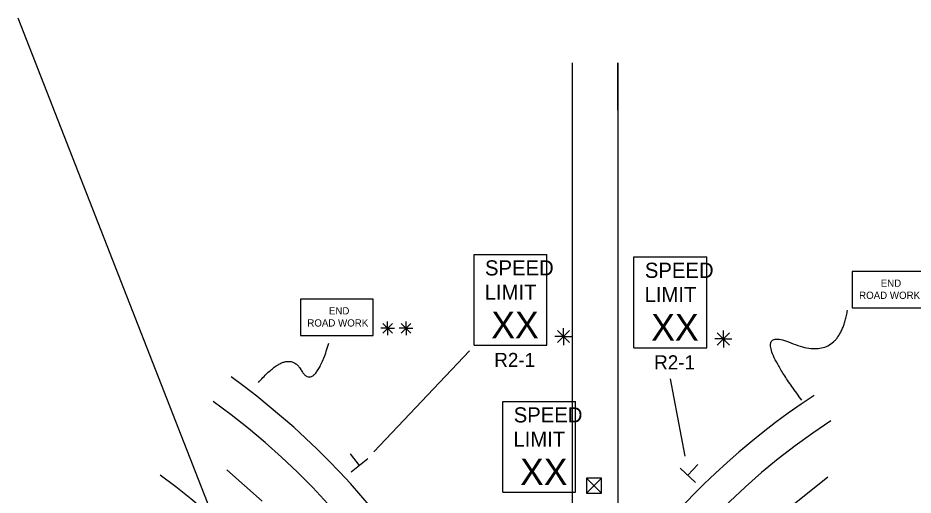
# Model space of a CAD drawing. Extents: x 16486 to 19505, y 5576 to 6998.
# Drawn here: x 16688.1 to 17160.6, y 6745.9 to 6997.8 of the extents above; entities that cross this region are included whole.
import ezdxf

# ---------------------------------------------------------------- set-up
doc = ezdxf.new("R2010")
doc.units = 0
for name, color, linetype in [('ALI_LEGAL_EX', 7, 'Continuous'), ('PAVT_EDGE_EX', 7, 'Continuous'), ('TRAFFIC_SIGNS_PR', 7, 'Continuous'), ('TYPICAL_TEXT_DIMEN_PR', 7, 'Continuous')]:
    doc.layers.add(name, color=color, linetype=linetype)

msp = doc.modelspace()

# ---------------------------------------------------------------- linework, layer by layer
at = {"layer": 'ALI_LEGAL_EX'}
for p, q in [((16688.08, 6997.81), (16910.11, 6429.44)), ((16980.68, 6974.12), (16980.68, 6155.98)), ((17004.68, 6974.12), (17004.68, 6155.98)), ((16980.68, 6922.21), (16980.68, 6058.3)), ((17004.68, 6922.21), (17004.68, 6058.3))]:
    msp.add_line(p, q, dxfattribs=at)
for points in [[(17004.68, 6949.12), (17004.68, 6974.12)], [(16817.07, 6742.72), (16798.4, 6759.35)], [(17096.1, 6739.95), (17115.56, 6755.65)]]:
    msp.add_lwpolyline(points, dxfattribs=at)
at = {"layer": 'PAVT_EDGE_EX'}
for centre, radius, start, end in [((16564.4, 6480.53), 404, 15.917, 54.2283), ((16564.4, 6480.53), 388, 0, 54.2283), ((17316.4, 6480.53), 380, 123.1879, 163.0483), ((17316.4, 6480.53), 364, 123.1879, 180), ((16564.4, 6480.53), 340, 0, 54.2283)]:
    msp.add_arc(centre, radius, start, end, dxfattribs=at)
at = {"layer": 'TRAFFIC_SIGNS_PR'}
for p, q in [((16928.82, 6873), (16967.22, 6873)), ((16928.82, 6825), (16928.82, 6873)), ((16967.22, 6825), (16967.22, 6873)), ((17013.23, 6871.74), (17051.63, 6871.74)), ((17013.23, 6823.74), (17013.23, 6871.74)), ((17051.63, 6823.74), (17051.63, 6871.74)), ((16928.82, 6825), (16967.22, 6825)), ((17013.23, 6823.74), (17051.63, 6823.74)), ((16944, 6795.43), (16982.4, 6795.43)), ((16944, 6747.43), (16944, 6795.43)), ((16982.4, 6747.43), (16982.4, 6795.43)), ((16944, 6747.43), (16982.4, 6747.43))]:
    msp.add_line(p, q, dxfattribs=at)
for points in [[(17128.46, 6844.75), (17166.86, 6844.75), (17166.86, 6863.95), (17128.46, 6863.95)], [(16837.22, 6830.16), (16875.62, 6830.16), (16875.62, 6849.36), (16837.22, 6849.36)]]:
    msp.add_lwpolyline(points, close=True, dxfattribs=at)
at = {"layer": 'TYPICAL_TEXT_DIMEN_PR'}
for p, q in [((16883.17, 6833.98), (16883.17, 6837.54)), ((16892.92, 6833.98), (16892.92, 6837.54)), ((16883.17, 6833.98), (16879.55, 6833.98)), ((16880.62, 6836.53), (16885.72, 6831.43)), ((16885.72, 6836.53), (16880.62, 6831.43)), ((16883.17, 6833.98), (16885.72, 6833.98)), ((16883.17, 6833.98), (16886.76, 6833.98)), ((16883.17, 6833.98), (16883.17, 6830.38)), ((16892.92, 6833.98), (16889.29, 6833.98)), ((16890.37, 6836.53), (16895.47, 6831.43)), ((16895.47, 6836.53), (16890.37, 6831.43)), ((16892.92, 6833.98), (16895.47, 6833.98)), ((16892.92, 6833.98), (16896.5, 6833.98)), ((16892.92, 6833.98), (16892.92, 6830.38)), ((16972.82, 6832.8), (16979.2, 6826.43)), ((16979.2, 6832.8), (16972.82, 6826.43)), ((16976.01, 6829.62), (16976.01, 6834.07)), ((17060.42, 6828.35), (17060.42, 6832.81)), ((16976.01, 6829.62), (16971.48, 6829.62)), ((16976.01, 6829.62), (16979.2, 6829.62)), ((16976.01, 6829.62), (16980.49, 6829.62)), ((16976.01, 6829.62), (16976.01, 6825.12)), ((17060.42, 6828.35), (17055.88, 6828.35)), ((17057.23, 6831.54), (17063.6, 6825.16)), ((17063.6, 6831.54), (17057.23, 6825.16)), ((17060.42, 6828.35), (17063.6, 6828.35)), ((17060.42, 6828.35), (17064.89, 6828.35)), ((17060.42, 6828.35), (17060.42, 6823.85)), ((16926.42, 6822.03), (16875.94, 6768.85)), ((17040.24, 6766.41), (17032.44, 6807.29)), ((16868.44, 6761.57), (16863.56, 6767.65)), ((16872.82, 6765.09), (16864.05, 6758.06)), ((17041.66, 6756.39), (17046.96, 6762.1)), ((17045.78, 6752.57), (17037.54, 6760.22)), ((16988.15, 6754.9), (16996.15, 6746.9)), ((16988.15, 6746.9), (16996.15, 6754.9))]:
    msp.add_line(p, q, dxfattribs=at)
msp.add_lwpolyline([(16988.15, 6754.9), (16988.15, 6746.9), (16996.15, 6746.9), (16996.15, 6754.9)], close=True, dxfattribs=at)
for points in [[(17101.86, 6795.98), (17071.58, 6836.6), (17121.54, 6815.63), (17125.94, 6843.59)], [(16815.05, 6805.35), (16830.8, 6823.7), (16844.29, 6800.22), (16852.21, 6826.08)]]:
    msp.add_open_spline(points, degree=2, dxfattribs=at)

# ---------------------------------------------------------------- texts
at = {"layer": 'TRAFFIC_SIGNS_PR'}
for s, height, p in [('SPEED', 8, (16934.59, 6861.86)), ('SPEED', 8, (17018.99, 6860.6)), ('LIMIT', 8, (16934.43, 6849.06)), ('LIMIT', 8, (17018.83, 6847.8)), ('END', 3.831, (17143.46, 6855.88)), ('ROAD WORK', 3.831, (17132.07, 6849.49)), ('END', 3.831, (16852.22, 6841.28)), ('XX', 14.031, (16937.93, 6828.76)), ('XX', 14.031, (17022.34, 6827.49)), ('ROAD WORK', 3.831, (16840.83, 6834.9)), ('R2-1', 7.44, (16939.5, 6813.56)), ('R2-1', 7.44, (17023.9, 6812.3)), ('SPEED', 8, (16949.76, 6784.29)), ('LIMIT', 8, (16949.6, 6771.49)), ('XX', 14.031, (16953.11, 6751.19))]:
    msp.add_text(s, height=height, dxfattribs=at).set_placement(p)

doc.saveas('drawing.dxf')
